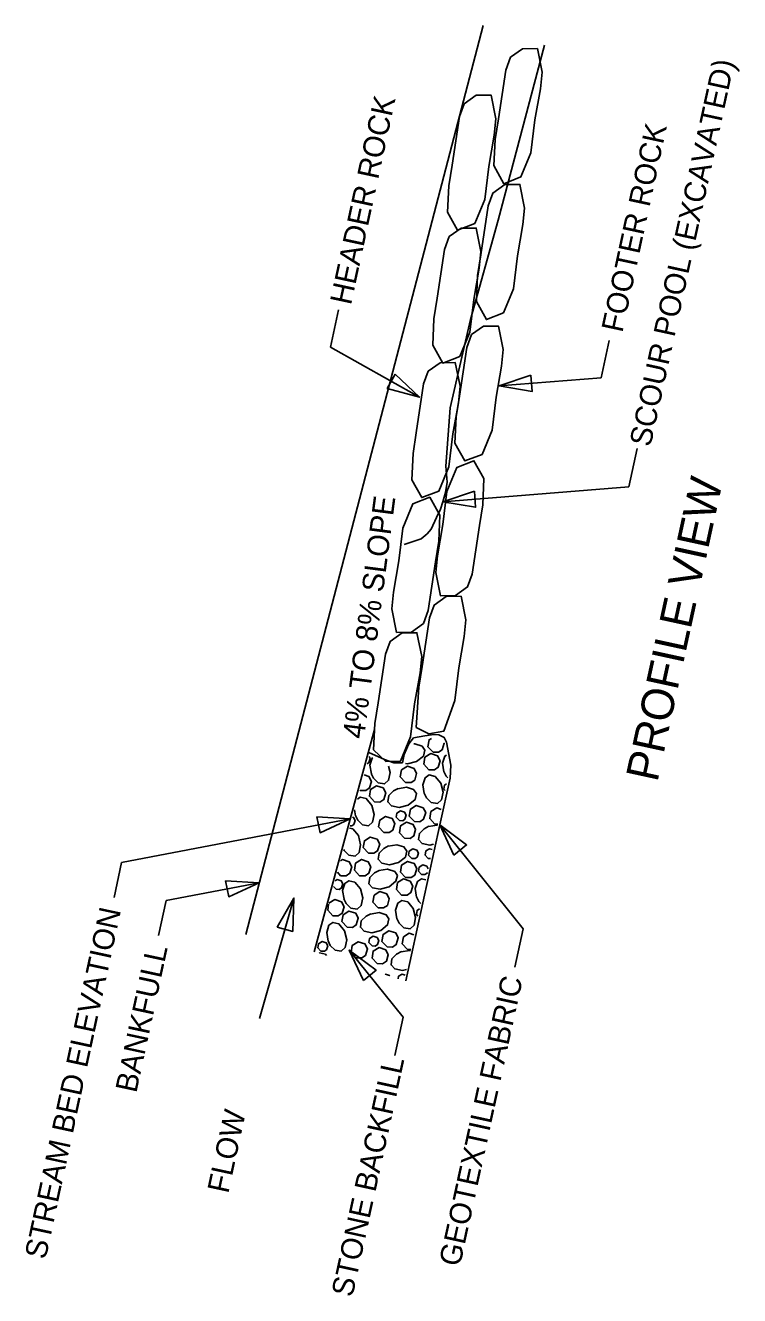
# Model space of a CAD drawing. Extents: x 2126110 to 2128246, y 1804858 to 1811658.
# Drawn here: x 2126229 to 2126889, y 1810482 to 1811658 of the extents above; entities that cross this region are included whole.
import ezdxf

# ---------------------------------------------------------------- set-up
doc = ezdxf.new("R2010")
doc.units = 0
for name, color, linetype in [('1', 7, 'Continuous'), ('42', 7, 'Continuous'), ('DET-EARTH', 7, 'Continuous'), ('Old_Level_1', 7, 'Continuous')]:
    doc.layers.add(name, color=color, linetype=linetype)

msp = doc.modelspace()

# ---------------------------------------------------------------- linework, layer by layer
at = {"layer": '1'}
for p, q in [((2126708.9, 1811639.3), (2126665.9, 1811477.3)), ((2126665.9, 1811477.2), (2126640.4, 1811385.5)), ((2126640.4, 1811385.4), (2126621.7, 1811303.8)), ((2126621.7, 1811303.6), (2126617.6, 1811249.7)), ((2126794.6, 1811266.1), (2126786.8, 1811230.5)), ((2126617.6, 1811249.7), (2126618.7, 1811234.9)), ((2126618.7, 1811234.9), (2126617.2, 1811225.3)), ((2126617.2, 1811225.3), (2126614.7, 1811216.7)), ((2126612.6, 1811209.9), (2126608.9, 1811202.2)), ((2126614.7, 1811216.7), (2126612.6, 1811209.9)), ((2126608.9, 1811202.2), (2126603.9, 1811191.5)), ((2126600.3, 1811187), (2126594.7, 1811182.3)), ((2126603.9, 1811191.5), (2126600.3, 1811187)), ((2126594.7, 1811182.3), (2126579.1, 1811177.2))]:
    msp.add_line(p, q, dxfattribs=at)
for centre, start, end in [((2126664.2, 1811477.7), 344.457, 345.1438), ((2126642.1, 1811385), 164.457, 167.1099), ((2126623.4, 1811303.4), 167.1099, 175.6848)]:
    msp.add_arc(centre, 1.78, start, end, dxfattribs=at)
at = {"layer": '42'}
for points in [[(2126705.2, 1811599), (2126700.1, 1811570.1), (2126696.4, 1811539.6), (2126687.1, 1811517.4), (2126671.3, 1811511.1), (2126662.1, 1811527.8), (2126663.2, 1811552), (2126666.2, 1811571.2), (2126673, 1811616.2), (2126677.3, 1811628.1), (2126688.4, 1811636), (2126688.4, 1811636), (2126702.3, 1811636.1), (2126706.7, 1811614.3), (2126705.2, 1811599)], [(2126705.2, 1811599), (2126700.1, 1811570.1), (2126696.4, 1811539.6), (2126687.1, 1811517.4), (2126671.3, 1811511.1), (2126662.1, 1811527.8), (2126663.2, 1811552), (2126666.2, 1811571.2), (2126673, 1811616.2), (2126677.3, 1811628.1), (2126688.4, 1811636), (2126688.4, 1811636), (2126702.3, 1811636.1), (2126706.7, 1811614.3), (2126705.2, 1811599)], [(2126619.3, 1811484.7), (2126620.4, 1811509), (2126623.4, 1811528.1), (2126630.2, 1811573.2), (2126634.5, 1811585), (2126645.6, 1811593), (2126645.6, 1811593), (2126659.5, 1811593.1), (2126663.9, 1811571.2), (2126662.4, 1811555.9)], [(2126619.3, 1811484.7), (2126620.4, 1811509), (2126623.4, 1811528.1), (2126630.2, 1811573.2), (2126634.5, 1811585), (2126645.6, 1811593), (2126645.6, 1811593), (2126659.5, 1811593.1), (2126663.9, 1811571.2), (2126662.4, 1811555.9)], [(2126662.4, 1811555.9), (2126657.3, 1811527), (2126653.6, 1811496.5), (2126644.3, 1811474.3), (2126628.5, 1811468.1)], [(2126662.4, 1811555.9), (2126657.3, 1811527), (2126653.6, 1811496.5), (2126644.3, 1811474.3), (2126628.5, 1811468.1)], [(2126689, 1811473.3), (2126683.9, 1811444.3), (2126680.2, 1811413.9), (2126670.9, 1811391.6), (2126655.2, 1811385.4), (2126645.9, 1811402.1), (2126647, 1811426.3), (2126650, 1811445.4), (2126656.8, 1811490.5), (2126661.2, 1811502.4), (2126672.3, 1811510.3), (2126672.3, 1811510.3), (2126686.1, 1811510.4), (2126690.5, 1811488.6), (2126689, 1811473.3)], [(2126689, 1811473.3), (2126683.9, 1811444.3), (2126680.2, 1811413.9), (2126670.9, 1811391.6), (2126655.2, 1811385.4), (2126645.9, 1811402.1), (2126647, 1811426.3), (2126650, 1811445.4), (2126656.8, 1811490.5), (2126661.2, 1811502.4), (2126672.3, 1811510.3), (2126672.3, 1811510.3), (2126686.1, 1811510.4), (2126690.5, 1811488.6), (2126689, 1811473.3)], [(2126628.5, 1811468.1), (2126619.3, 1811484.7)], [(2126628.5, 1811468.1), (2126619.3, 1811484.7)], [(2126648.6, 1811433), (2126643.5, 1811404), (2126639.8, 1811373.6), (2126630.5, 1811351.3), (2126614.8, 1811345.1), (2126605.5, 1811361.8), (2126606.6, 1811386), (2126609.6, 1811405.1), (2126616.4, 1811450.3), (2126620.8, 1811462.1), (2126631.9, 1811470), (2126631.9, 1811470), (2126645.7, 1811470.1), (2126650.1, 1811448.3), (2126648.6, 1811433)], [(2126648.6, 1811433), (2126643.5, 1811404), (2126639.8, 1811373.6), (2126630.5, 1811351.3), (2126614.8, 1811345.1), (2126605.5, 1811361.8), (2126606.6, 1811386), (2126609.6, 1811405.1), (2126616.4, 1811450.3), (2126620.8, 1811462.1), (2126631.9, 1811470), (2126631.9, 1811470), (2126645.7, 1811470.1), (2126650.1, 1811448.3), (2126648.6, 1811433)], [(2126669.2, 1811342.3), (2126664.1, 1811313.4), (2126660.4, 1811282.9), (2126651.1, 1811260.6), (2126635.3, 1811254.5), (2126626, 1811271.1), (2126627.2, 1811295.3), (2126630.2, 1811314.5), (2126637, 1811359.6), (2126641.3, 1811371.4), (2126652.4, 1811379.3), (2126652.4, 1811379.3), (2126666.3, 1811379.4), (2126670.7, 1811357.6), (2126669.2, 1811342.3)], [(2126669.2, 1811342.3), (2126664.1, 1811313.4), (2126660.4, 1811282.9), (2126651.1, 1811260.6), (2126635.3, 1811254.5), (2126626, 1811271.1), (2126627.2, 1811295.3), (2126630.2, 1811314.5), (2126637, 1811359.6), (2126641.3, 1811371.4), (2126652.4, 1811379.3), (2126652.4, 1811379.3), (2126666.3, 1811379.4), (2126670.7, 1811357.6), (2126669.2, 1811342.3)], [(2126629.2, 1811308.4), (2126624.2, 1811279.6), (2126620.5, 1811249), (2126611.2, 1811226.7), (2126595.4, 1811220.6), (2126586.1, 1811237.2), (2126587.3, 1811261.5), (2126590.3, 1811280.6), (2126597, 1811325.8), (2126601.4, 1811337.6), (2126612.5, 1811345.4), (2126612.5, 1811345.4), (2126626.4, 1811345.5), (2126630.8, 1811323.7), (2126629.2, 1811308.4)], [(2126629.2, 1811308.4), (2126624.2, 1811279.6), (2126620.5, 1811249), (2126611.2, 1811226.7), (2126595.4, 1811220.6), (2126586.1, 1811237.2), (2126587.3, 1811261.5), (2126590.3, 1811280.6), (2126597, 1811325.8), (2126601.4, 1811337.6), (2126612.5, 1811345.4), (2126612.5, 1811345.4), (2126626.4, 1811345.5), (2126630.8, 1811323.7), (2126629.2, 1811308.4)], [(2126609.8, 1811166.7), (2126614.9, 1811195.6), (2126618.6, 1811226.1), (2126627.8, 1811248.5), (2126643.6, 1811254.7), (2126652.9, 1811238.2), (2126651.7, 1811213.9), (2126648.8, 1811194.8), (2126642.1, 1811149.7), (2126637.7, 1811137.9), (2126626.7, 1811129.9), (2126626.7, 1811129.9), (2126612.8, 1811129.6), (2126608.4, 1811151.4), (2126609.8, 1811166.7)], [(2126609.8, 1811166.7), (2126614.9, 1811195.6), (2126618.6, 1811226.1), (2126627.8, 1811248.5), (2126643.6, 1811254.7), (2126652.9, 1811238.2), (2126651.7, 1811213.9), (2126648.8, 1811194.8), (2126642.1, 1811149.7), (2126637.7, 1811137.9), (2126626.7, 1811129.9), (2126626.7, 1811129.9), (2126612.8, 1811129.6), (2126608.4, 1811151.4), (2126609.8, 1811166.7)], [(2126569.1, 1811133.1), (2126574.2, 1811162), (2126577.8, 1811192.4), (2126587, 1811214.8), (2126602.8, 1811221), (2126612.1, 1811204.5), (2126611, 1811180.3), (2126608, 1811161.1), (2126601.3, 1811116), (2126597, 1811104.2), (2126585.9, 1811096.2), (2126585.9, 1811096.2), (2126572, 1811095.9), (2126567.6, 1811117.8), (2126569.1, 1811133.1)], [(2126569.1, 1811133.1), (2126574.2, 1811162), (2126577.8, 1811192.4), (2126587, 1811214.8), (2126602.8, 1811221), (2126612.1, 1811204.5), (2126611, 1811180.3), (2126608, 1811161.1), (2126601.3, 1811116), (2126597, 1811104.2), (2126585.9, 1811096.2), (2126585.9, 1811096.2), (2126572, 1811095.9), (2126567.6, 1811117.8), (2126569.1, 1811133.1)], [(2126634.6, 1811092.1), (2126629.5, 1811063.2), (2126625.8, 1811032.7), (2126615.9, 1811004.6), (2126602, 1811002.1), (2126590.2, 1811008), (2126592.7, 1811045.2), (2126595.6, 1811064.3), (2126602.4, 1811109.4), (2126606.7, 1811121.2), (2126617.9, 1811129.2), (2126617.9, 1811129.2), (2126631.7, 1811129.3), (2126636.1, 1811107.4), (2126634.6, 1811092.1)], [(2126634.6, 1811092.1), (2126629.5, 1811063.2), (2126625.8, 1811032.7), (2126615.9, 1811004.6), (2126602, 1811002.1), (2126590.2, 1811008), (2126592.7, 1811045.2), (2126595.6, 1811064.3), (2126602.4, 1811109.4), (2126606.7, 1811121.2), (2126617.9, 1811129.2), (2126617.9, 1811129.2), (2126631.7, 1811129.3), (2126636.1, 1811107.4), (2126634.6, 1811092.1)], [(2126593.8, 1811058.4), (2126588.7, 1811029.6), (2126585, 1810999.1), (2126575.7, 1810976.8), (2126562.1, 1810976.4), (2126550.7, 1810987.2), (2126551.9, 1811011.5), (2126554.9, 1811030.7), (2126561.7, 1811075.7), (2126566, 1811087.5), (2126577.1, 1811095.5), (2126577.1, 1811095.5), (2126590.9, 1811095.6), (2126595.3, 1811073.7), (2126593.8, 1811058.4)], [(2126593.8, 1811058.4), (2126588.7, 1811029.6), (2126585, 1810999.1), (2126575.7, 1810976.8), (2126562.1, 1810976.4), (2126550.7, 1810987.2), (2126551.9, 1811011.5), (2126554.9, 1811030.7), (2126561.7, 1811075.7), (2126566, 1811087.5), (2126577.1, 1811095.5), (2126577.1, 1811095.5), (2126590.9, 1811095.6), (2126595.3, 1811073.7), (2126593.8, 1811058.4)]]:
    msp.add_lwpolyline(points, dxfattribs=at)
at = {"layer": 'Old_Level_1'}
for p, q in [((2126652.2, 1811657.6), (2126432.6, 1810816.3)), ((2126518.3, 1811394.3), (2126510.8, 1811359.7)), ((2126593.2, 1811313.5), (2126510.8, 1811359.7)), ((2126768.8, 1811366.1), (2126761.2, 1811331.5)), ((2126667, 1811324), (2126761.2, 1811331.5)), ((2126614.7, 1811216.7), (2126786.8, 1811230.5)), ((2126495.9, 1810800.3), (2126551.6, 1811006.1)), ((2126587.8, 1810998.3), (2126583.3, 1810992.7)), ((2126598.2, 1811000), (2126587.8, 1810998.3)), ((2126606.5, 1811001.5), (2126598.2, 1811000)), ((2126611.1, 1811001.2), (2126606.5, 1811001.5)), ((2126560.9, 1810978.3), (2126546.3, 1810984.8)), ((2126579.2, 1810982.9), (2126577.5, 1810975.3)), ((2126583.3, 1810992.7), (2126579.2, 1810982.9)), ((2126622.3, 1810972.9), (2126618.2, 1810994.3)), ((2126569.5, 1810975.1), (2126560.9, 1810978.3)), ((2126577.5, 1810975.3), (2126569.5, 1810975.1)), ((2126621.6, 1810961), (2126622.3, 1810972.9)), ((2126612.1, 1810917.9), (2126621.6, 1810961)), ((2126538.4, 1810949.7), (2126538.1, 1810950)), ((2126534, 1810926.2), (2126533.1, 1810931.8)), ((2126529.2, 1810923.4), (2126317.6, 1810882.9)), ((2126580.7, 1810773.3), (2126612.1, 1810917.9)), ((2126610.2, 1810918.4), (2126607.4, 1810918.5)), ((2126612.1, 1810917.9), (2126689.3, 1810821.6)), ((2126310.6, 1810850.6), (2126317.6, 1810882.9)), ((2126317.6, 1810882.9), (2126310.6, 1810850.6)), ((2126603.4, 1810886.6), (2126601.4, 1810886.7)), ((2126520.3, 1810870.7), (2126517.3, 1810873.9)), ((2126444.8, 1810864.2), (2126358.9, 1810847.8)), ((2126516, 1810858.1), (2126513.6, 1810860.6)), ((2126351.9, 1810815.4), (2126358.9, 1810847.8)), ((2126358.9, 1810847.8), (2126351.9, 1810815.4)), ((2126477, 1810850), (2126445.1, 1810738.4)), ((2126681.6, 1810786), (2126689.3, 1810821.6)), ((2126528.3, 1810801.9), (2126578.1, 1810739.8)), ((2126585.2, 1810802.4), (2126582.1, 1810802.5)), ((2126570.3, 1810704.2), (2126578.1, 1810739.8))]:
    msp.add_line(p, q, dxfattribs=at)
for points in [[(2126570.7, 1811334.7), (2126593.2, 1811313.5), (2126563.4, 1811321.6)], [(2126696.3, 1811333.8), (2126667, 1811324), (2126697.5, 1811318.9)], [(2126644, 1811226.6), (2126614.7, 1811216.7), (2126645.2, 1811211.6)], [(2126498.4, 1810925.1), (2126529.2, 1810923.4), (2126501.2, 1810910.4)], [(2126625, 1810889.8), (2126612.1, 1810917.9), (2126636.8, 1810899.2)], [(2126413.9, 1810865.9), (2126444.8, 1810864.2), (2126416.8, 1810851.2)], [(2126461.5, 1810823.2), (2126477, 1810850), (2126475.9, 1810819.1)], [(2126541.3, 1810773.8), (2126528.3, 1810801.9), (2126553, 1810783.2)]]:
    msp.add_lwpolyline(points, close=True, dxfattribs=at)
for points in [[(2126605.8, 1810985), (2126601, 1810990.1), (2126602.1, 1810996.5), (2126604.2, 1810997.8)], [(2126618.2, 1810994.3), (2126616.1, 1810998.7), (2126611.1, 1811001.2)], [(2126587.9, 1810992.6), (2126589, 1810992.7), (2126595.6, 1810990.7), (2126598.2, 1810986.9), (2126596.9, 1810981.4), (2126590.6, 1810976.3), (2126582.2, 1810974.1), (2126580.4, 1810974.5)], [(2126602, 1810968.8), (2126597.3, 1810974), (2126598.3, 1810980.3), (2126603.8, 1810983.7), (2126610, 1810981.7), (2126612.4, 1810977.1), (2126610.6, 1810971), (2126607.1, 1810968.7), (2126602, 1810968.8)], [(2126616.1, 1810993.3), (2126616.1, 1810993.3), (2126614.3, 1810987.2), (2126610.9, 1810984.9), (2126605.8, 1810985)], [(2126546.6, 1810981), (2126547.5, 1810979.1), (2126546.5, 1810975.4), (2126544.7, 1810974.3)], [(2126548.7, 1810964.9), (2126547.4, 1810972.9), (2126549.5, 1810979.6), (2126550, 1810979.9)], [(2126564.5, 1810972.1), (2126566, 1810966.2), (2126564.6, 1810959.1), (2126560.9, 1810955.7), (2126555.1, 1810956.5), (2126550.8, 1810960.9), (2126548.6, 1810965.3)], [(2126580.3, 1810957), (2126575.5, 1810962.2), (2126576.6, 1810968.6), (2126582, 1810972), (2126588.3, 1810969.9), (2126590.6, 1810965.3), (2126588.8, 1810959.2), (2126585.4, 1810956.9), (2126580.3, 1810957)], [(2126615.9, 1810966.7), (2126614.6, 1810974.7), (2126616.6, 1810981.4), (2126618.1, 1810982.3)], [(2126541.9, 1810964), (2126546.4, 1810962.6), (2126548.8, 1810958), (2126547, 1810951.9), (2126543.5, 1810949.6), (2126538.4, 1810949.7)], [(2126597.7, 1810946.7), (2126596.4, 1810954.7), (2126598.5, 1810961.4), (2126602.2, 1810963.9), (2126607.7, 1810962.6), (2126612.9, 1810956.4), (2126615, 1810948), (2126613.6, 1810940.9), (2126609.9, 1810937.5), (2126604.1, 1810938.3), (2126599.7, 1810942.7), (2126597.6, 1810947.1)], [(2126619.4, 1810961.2), (2126617.9, 1810962.7), (2126615.8, 1810967.1)], [(2126551.6, 1810939), (2126546.9, 1810944.2), (2126547.9, 1810950.6), (2126553.4, 1810953.9), (2126559.6, 1810951.9), (2126562, 1810947.3), (2126560.2, 1810941.2), (2126556.7, 1810938.9), (2126551.6, 1810939)], [(2126573.2, 1810951.2), (2126581.2, 1810952.5), (2126587.8, 1810950.4), (2126590.4, 1810946.7), (2126589.1, 1810941.2), (2126582.8, 1810936), (2126574.4, 1810933.9), (2126567.3, 1810935.3), (2126563.9, 1810939), (2126564.8, 1810944.8), (2126569.1, 1810949.1), (2126573.5, 1810951.3)], [(2126617, 1810949.5), (2126615.8, 1810950.8), (2126616.4, 1810954.6), (2126618.3, 1810955.8)], [(2126535.8, 1810941.5), (2126538.5, 1810943.4), (2126544, 1810942.1), (2126549.2, 1810935.8), (2126551.3, 1810927.4), (2126549.9, 1810920.3), (2126546.2, 1810916.9), (2126540.4, 1810917.8), (2126536.1, 1810922.1), (2126533.9, 1810926.5)], [(2126531.2, 1810925), (2126532.3, 1810924.6), (2126533.7, 1810921.9), (2126532.6, 1810918.2), (2126530.5, 1810916.8), (2126529, 1810916.9)], [(2126560.2, 1810910.7), (2126555.4, 1810915.8), (2126556.4, 1810922.2), (2126561.9, 1810925.6), (2126568.1, 1810923.6), (2126570.5, 1810919), (2126568.7, 1810912.9), (2126565.2, 1810910.6), (2126560.2, 1810910.7)], [(2126574.6, 1810921.7), (2126571.8, 1810924.8), (2126572.4, 1810928.6), (2126575.7, 1810930.7), (2126579.4, 1810929.4), (2126580.8, 1810926.7), (2126579.7, 1810923), (2126577.7, 1810921.6), (2126574.6, 1810921.7)], [(2126588.6, 1810920.8), (2126583.8, 1810925.9), (2126584.9, 1810932.3), (2126590.3, 1810935.7), (2126596.6, 1810933.6), (2126599, 1810929.1), (2126597.1, 1810922.9), (2126593.7, 1810920.6), (2126588.6, 1810920.8)], [(2126607.4, 1810918.5), (2126602.7, 1810923.6), (2126603.7, 1810930), (2126609.2, 1810933.4), (2126613.2, 1810932.1)], [(2126528.4, 1810914.8), (2126531.5, 1810914), (2126536.7, 1810907.8), (2126538.8, 1810899.4), (2126537.4, 1810892.3), (2126533.7, 1810888.9), (2126527.9, 1810889.7), (2126523.6, 1810894.1), (2126523.1, 1810895.1)], [(2126579.4, 1810905.3), (2126574.6, 1810910.5), (2126575.7, 1810916.9), (2126581.1, 1810920.2), (2126587.4, 1810918.2), (2126589.7, 1810913.6), (2126587.9, 1810907.5), (2126584.5, 1810905.2), (2126579.4, 1810905.3)], [(2126606.2, 1810899.8), (2126602.8, 1810899), (2126595.6, 1810900.4), (2126592.2, 1810904.1), (2126593.1, 1810909.9), (2126597.5, 1810914.2), (2126601.8, 1810916.4)], [(2126601.5, 1810916.3), (2126609.5, 1810917.6), (2126610, 1810917.4)], [(2126546, 1810891.5), (2126541.2, 1810896.7), (2126542.3, 1810903.1), (2126547.7, 1810906.4), (2126554, 1810904.4), (2126556.4, 1810899.8), (2126554.5, 1810893.7), (2126551.1, 1810891.4), (2126546, 1810891.5)], [(2126564.3, 1810898), (2126572.3, 1810899.3), (2126578.9, 1810897.3), (2126581.5, 1810893.5), (2126580.2, 1810888), (2126573.9, 1810882.9), (2126565.6, 1810880.7), (2126558.4, 1810882.2), (2126555, 1810885.9), (2126555.9, 1810891.6), (2126560.3, 1810896), (2126564.6, 1810898.2)], [(2126586.1, 1810886.5), (2126583.2, 1810889.6), (2126583.8, 1810893.5), (2126587.1, 1810895.5), (2126590.9, 1810894.3), (2126592.3, 1810891.5), (2126591.2, 1810887.9), (2126589.1, 1810886.5), (2126586.1, 1810886.5)], [(2126601.4, 1810886.7), (2126598.6, 1810889.8), (2126599.2, 1810893.6), (2126602.5, 1810895.6), (2126605.1, 1810894.8)], [(2126520.2, 1810884.5), (2126522, 1810885.6), (2126528.2, 1810883.6), (2126530.6, 1810879), (2126528.8, 1810872.9), (2126525.3, 1810870.6), (2126520.3, 1810870.7)], [(2126537.8, 1810870.7), (2126533.1, 1810875.9), (2126534.1, 1810882.3), (2126539.6, 1810885.7), (2126545.8, 1810883.6), (2126548.2, 1810879), (2126546.4, 1810872.9), (2126542.9, 1810870.6), (2126537.8, 1810870.7)], [(2126580.4, 1810869), (2126575.7, 1810874.1), (2126576.7, 1810880.5), (2126582.2, 1810883.9), (2126588.4, 1810881.9), (2126590.8, 1810877.3), (2126589, 1810871.2), (2126585.5, 1810868.9), (2126580.4, 1810869)], [(2126595.2, 1810871.8), (2126592.4, 1810874.9), (2126593, 1810878.7), (2126596.3, 1810880.7), (2126600, 1810879.5), (2126601.3, 1810877.1)], [(2126515.1, 1810865.8), (2126517, 1810867.1), (2126520.8, 1810865.8), (2126522.2, 1810863.1), (2126521.1, 1810859.4), (2126519, 1810858), (2126516, 1810858.1)], [(2126523.4, 1810848.9), (2126522.1, 1810856.9), (2126524.1, 1810863.6), (2126527.9, 1810866.1), (2126533.4, 1810864.8), (2126538.6, 1810858.6), (2126540.7, 1810850.2), (2126539.3, 1810843.1), (2126535.5, 1810839.7), (2126529.8, 1810840.5), (2126525.4, 1810844.9), (2126523.3, 1810849.3)], [(2126555.6, 1810875.4), (2126563.6, 1810876.8), (2126570.3, 1810874.7), (2126572.8, 1810870.9), (2126571.5, 1810865.5), (2126565.3, 1810860.3), (2126556.9, 1810858.2), (2126549.7, 1810859.6), (2126546.4, 1810863.3), (2126547.2, 1810869.1), (2126551.6, 1810873.4), (2126555.9, 1810875.6)], [(2126576.7, 1810852.8), (2126571.9, 1810858), (2126572.9, 1810864.4), (2126578.4, 1810867.7), (2126584.6, 1810865.7), (2126587, 1810861.1), (2126585.2, 1810855), (2126581.7, 1810852.7), (2126576.7, 1810852.8)], [(2126590.5, 1810850.7), (2126589.2, 1810858.7), (2126591.3, 1810865.4), (2126595, 1810867.9), (2126599.1, 1810867)], [(2126600.6, 1810873.8), (2126600.4, 1810873.1), (2126598.3, 1810871.7), (2126595.2, 1810871.8)], [(2126554.9, 1810841), (2126550.2, 1810846.2), (2126551.2, 1810852.6), (2126556.7, 1810856), (2126562.9, 1810853.9), (2126565.3, 1810849.4), (2126563.5, 1810843.2), (2126560, 1810840.9), (2126554.9, 1810841.1)], [(2126513.1, 1810833.7), (2126508.3, 1810838.9), (2126509.2, 1810844.5)], [(2126509.4, 1810845.3), (2126514.8, 1810848.6), (2126521, 1810846.6), (2126523.4, 1810842), (2126521.6, 1810835.9), (2126518.1, 1810833.6), (2126513.1, 1810833.7)], [(2126572.4, 1810830.7), (2126571.1, 1810838.7), (2126573.1, 1810845.4), (2126576.9, 1810847.9), (2126582.4, 1810846.6), (2126587.5, 1810840.4), (2126589.7, 1810832), (2126588.2, 1810824.9), (2126584.5, 1810821.5), (2126578.8, 1810822.3), (2126574.4, 1810826.7), (2126572.2, 1810831.1)], [(2126594.4, 1810844.9), (2126592.6, 1810846.7), (2126590.4, 1810851.1)], [(2126526.3, 1810823), (2126521.5, 1810828.2), (2126522.5, 1810834.6), (2126528, 1810837.9), (2126534.2, 1810835.9), (2126536.6, 1810831.3), (2126534.8, 1810825.2), (2126531.4, 1810822.9), (2126526.3, 1810823)], [(2126547.8, 1810835.2), (2126555.8, 1810836.5), (2126562.5, 1810834.4), (2126565, 1810830.7), (2126563.7, 1810825.2), (2126557.5, 1810820), (2126549.1, 1810817.9), (2126541.9, 1810819.3), (2126538.6, 1810823), (2126539.4, 1810828.8), (2126543.8, 1810833.2), (2126548.2, 1810835.3)], [(2126591.8, 1810833.3), (2126590.4, 1810834.8), (2126591, 1810838.6), (2126593.3, 1810840)], [(2126508.7, 1810810.2), (2126507.4, 1810818.2), (2126509.4, 1810824.8), (2126513.2, 1810827.4), (2126518.7, 1810826.1), (2126523.8, 1810819.8), (2126526, 1810811.5), (2126524.5, 1810804.3), (2126520.8, 1810800.9), (2126515.1, 1810801.8), (2126510.7, 1810806.2), (2126508.6, 1810810.5)], [(2126563.2, 1810804.8), (2126558.5, 1810809.9), (2126559.5, 1810816.3), (2126565, 1810819.7), (2126571.2, 1810817.7), (2126573.6, 1810813.1), (2126571.8, 1810807), (2126568.3, 1810804.7), (2126563.2, 1810804.8)], [(2126502.1, 1810800.9), (2126499.3, 1810804), (2126499.9, 1810807.8), (2126503.2, 1810809.9), (2126506.9, 1810808.7), (2126508.3, 1810805.9), (2126507.3, 1810802.2), (2126505.2, 1810800.8), (2126502.1, 1810800.9)], [(2126534.8, 1810794.7), (2126530.1, 1810799.9), (2126531.1, 1810806.2), (2126536.6, 1810809.6), (2126542.8, 1810807.6), (2126545.2, 1810803), (2126543.4, 1810796.9), (2126539.9, 1810794.6), (2126534.8, 1810794.7)], [(2126549.3, 1810805.7), (2126546.4, 1810808.8), (2126547, 1810812.6), (2126550.3, 1810814.7), (2126554, 1810813.5), (2126555.5, 1810810.7), (2126554.4, 1810807), (2126552.3, 1810805.6), (2126549.3, 1810805.7)], [(2126582.1, 1810802.5), (2126577.3, 1810807.7), (2126578.3, 1810814), (2126583.8, 1810817.4), (2126588.1, 1810816)], [(2126500.3, 1810799.1), (2126500.7, 1810799.3), (2126506.2, 1810798), (2126507.2, 1810796.9)], [(2126554, 1810789.3), (2126549.3, 1810794.5), (2126550.3, 1810800.9), (2126555.8, 1810804.2), (2126562, 1810802.2), (2126564.4, 1810797.6), (2126562.6, 1810791.5), (2126559.1, 1810789.2), (2126554, 1810789.3)], [(2126581.2, 1810783.9), (2126577.4, 1810783), (2126570.3, 1810784.4), (2126566.9, 1810788.1), (2126567.8, 1810793.9), (2126572.1, 1810798.2), (2126576.5, 1810800.4)], [(2126576.1, 1810800.3), (2126584.2, 1810801.6), (2126584.9, 1810801.3)], [(2126561.5, 1810779.3), (2126561.8, 1810779.5), (2126565.5, 1810778.3), (2126565.7, 1810778)], [(2126573.5, 1810775.4), (2126573.8, 1810777.6), (2126577.1, 1810779.6), (2126580.1, 1810778.7)]]:
    msp.add_lwpolyline(points, dxfattribs=at)

# ---------------------------------------------------------------- texts
at = {"layer": '1'}
msp.add_text('SCOUR POOL (EXCAVATED)', height=20, rotation=77.6736, dxfattribs=at).set_placement((2126806.9, 1811266.8))
at = {"layer": 'DET-EARTH'}
msp.add_text('PROFILE VIEW ', height=30, rotation=77.7315, dxfattribs=at).set_placement((2126813.3, 1810956.5))
at = {"layer": 'Old_Level_1'}
for s, rotation, p in [('HEADER ROCK', 77.8264, (2126529.8, 1811398.1)), ('FOOTER ROCK', 77.8264, (2126780.9, 1811372.6)), ('4% TO 8% SLOPE', 82.5886, (2126541.9, 1810996.7)), ('STREAM BED ELEVATION', 77.8264, (2126247.3, 1810514.9)), ('BANKFULL', 77.8264, (2126331.2, 1810669)), ('GEOTEXTILE FABRIC', 77.6736, (2126630.6, 1810508.2)), ('STONE BACKFILL', 77.6736, (2126531.1, 1810479.9)), ('FLOW', 77.8264, (2126416.3, 1810575.9))]:
    msp.add_text(s, height=20, rotation=rotation, dxfattribs=at).set_placement(p)

doc.saveas('drawing.dxf')
